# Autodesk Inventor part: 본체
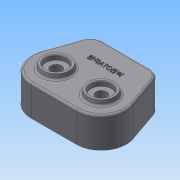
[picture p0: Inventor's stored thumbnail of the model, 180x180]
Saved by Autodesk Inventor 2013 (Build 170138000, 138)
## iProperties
Created: 2014-12
Part Number: 본체
Material: 일반
Document SubType Name: Modeling
Designer: Administrator
Density: 1 g/cm^3
Author: Administrator
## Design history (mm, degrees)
sketch "스케치1"
  geometry: L1 (47, 36)-(-47, 36); L2 (32.527, -68.527)-(-32.527, -68.527); L3 (47, 36)-(66.565, -20.803); L4 (-47, 36)-(-66.565, -20.803); A1 r 36 centre (32.527, -32.527) between (32.527, -68.527) and (66.565, -20.803); A2 r 36 centre (-32.527, -32.527) between (-66.565, -20.803) and (-32.527, -68.527); 3 further points
  constraints: 8 end point, 4 point on circle, 3 tangent, 2 centre point, 2 midpoint, 2 vertical alignment, 1 horizontal, 1 horizontal alignment
  dimensions: "d18" = 94 distance of L1.start L1.end; "d19" = 72 diameter of A1; "d20" = 72 diameter of A2; "d21" = 36 distance from line of point (0, 0) L1; "d22" = 46 distance of A1.centre point (0, 0); "d23" = 90 deg dimension on point (0, 0) A2.centre A1.centre; "d24" = 46 distance of A2.centre point (0, 0)
extrude "돌출1" new body sketch "스케치1" distance "d25" = 44; taper "d26" = 0 deg
sketch "스케치2"
  geometry: L1 (-43.434, 31)-(43.434, 31); L2 (43.434, 31)-(61.837, -22.432); L3 (-43.434, 31)-(-61.837, -22.432); L4 (-66.565, -20.803)-(-47, 36) reference; L5 (47, 36)-(66.565, -20.803) reference; L6 (-32.527, -63.527)-(32.527, -63.527); L7 (-47, 36)-(47, 36) reference; A1 r 36 centre (-32.527, -32.527) between (-66.565, -20.803) and (-32.527, -68.527) reference; A2 r 36 centre (32.527, -32.527) between (32.527, -68.527) and (66.565, -20.803) reference; A3 r 31 centre (-32.527, -32.527) between (-61.837, -22.432) and (-32.527, -63.527); A4 r 31 centre (32.527, -32.527) between (32.527, -63.527) and (61.837, -22.432); 1 further point
  constraints: 8 end point, 4 point on circle, 3 parallel, 3 tangent, 2 centre point, 2 coincident, 1 horizontal
  dimensions: "d29" = 5 distance between parallel lines of L4 L3; "d30" = 5 distance between parallel lines of L7 L1; "d31" = 5 distance between parallel lines of L2 L5
extrude "돌출2" cut sketch "스케치2" distance "d32" = 34; taper "d33" = 0 deg
sketch "스케치3"
  geometry: L1 (47, 36)-(-47, 36) reference; L2 (-47, 36)-(-66.565, -20.803) reference; L3 (-32.527, -68.527)-(32.527, -68.527) reference; L4 (66.565, -20.803)-(47, 36) reference; C1 r 20 at (-32.527, -32.527); C2 r 20 at (32.527, -32.527); A1 r 36 centre (-32.527, -32.527) between (-66.565, -20.803) and (-32.527, -68.527) reference; A2 r 36 centre (32.527, -32.527) between (32.527, -68.527) and (66.565, -20.803) reference; A3 r 36 centre (-32.527, -32.527) between (-66.565, -20.803) and (-32.527, -68.527) reference; A4 r 36 centre (32.527, -32.527) between (32.527, -68.527) and (66.565, -20.803) reference; 1 further point
  constraints: 2 centre point, 2 coincident
  dimensions: "d34" = 40 diameter of C1; "d35" = 40 diameter of C2
extrude "돌출3" join sketch "스케치3" distance "d36" = 7; taper "d37" = -10 deg
sketch "스케치4"
  geometry: A1 r 36 centre (-32.527, -32.527) between (-66.565, -20.803) and (-32.527, -68.527) reference; A2 r 36 centre (32.527, -32.527) between (32.527, -68.527) and (66.565, -20.803) reference; A3 r 24 centre (-32.527, -32.527) between (-21.111, -11.416) and (-11.416, -21.111); A4 r 24 centre (32.527, -32.527) between (11.416, -21.111) and (21.111, -11.416); A5 r 24 centre (0, 0) between (-11.416, -21.111) and (11.416, -21.111); A6 r 24 centre (0, 0) between (21.111, -11.416) and (-21.111, -11.416); 1 further point
  constraints: 8 point on circle, 4 centre point, 3 coincident
  dimensions: "d39" = 48 diameter of A3; "d40" = 48 diameter of A4; "d41" = 24 radius of A6; "d42" = 24 radius of A5
extrude "돌출4" join sketch "스케치4" distance "d43" = 11; taper "d44" = 0 deg
hole "구멍1" diameter "d47" = 20; stored, may be unused: countersink angle "d51" = 90 deg, drill point angle "d53" = 0 deg; dims "d45" = 10, "d46" = 10, "d48" = 6, "d49" = 40, "d50" = 12, "d52" = 15
hole "구멍2" diameter "d56" = 15.5; stored, may be unused: countersink angle "d60" = 90 deg, drill point angle "d62" = 0 deg; dims "d54" = 10, "d55" = 10, "d57" = 6, "d58" = 35, "d59" = 11, "d61" = 21
hole "구멍3" diameter "d65" = 15.5; stored, may be unused: countersink angle "d69" = 90 deg, drill point angle "d71" = 0 deg; dims "d63" = 10, "d64" = 10, "d66" = 6, "d67" = 35, "d68" = 11, "d70" = 21
sketch "스케치5"
  geometry: C1 r 18.766 at (0, 0) reference; C2 r 18.766 at (65.054, 0) reference; C3 r 15 at (0, 0); C4 r 15 at (65.054, 0); 1 further point
  constraints: 2 centre point, 2 coincident
  dimensions: "d72" = 30 diameter of C3; "d73" = 30 diameter of C4
extrude "돌출5" cut sketch "스케치5" distance "d74" = 7; taper "d75" = 0 deg
sketch "스케치6"
  geometry: L1 (-47, 36)-(47, 36) reference; L2 (32.527, -63.527)-(-32.527, -63.527) reference; L3 (-61.837, -22.432)-(-43.434, 31) reference; L4 (43.434, 31)-(61.837, -22.432) reference; A1 r 8 centre (-51.7, 7) between (-54.305, -0.564) and (-49.095, 14.564); A2 r 8 centre (51.7, 7) between (49.095, 14.564) and (54.305, -0.564); A3 r 8 centre (0, -63.527) between (8, -63.527) and (-8, -63.527); 2 further points
  constraints: 8 point on line, 6 point on circle, 3 centre point, 1 coincident, 1 horizontal alignment, 1 midpoint, 1 vertical alignment
  dimensions: "d76" = 16 diameter of A1; "d77" = 16 diameter of A2; "d78" = 29 distance from line of A2.centre L1; "d79" = 16 diameter of A3
extrude "돌출6" join sketch "스케치6" stored distance "d80" = 7; taper "d81" = 0 deg
fillet "모깎기1" dims "d82" = 18, "d83" = 13
sketch "스케치7"
  geometry: A1 r 8 centre (-51.7, 7) between (-54.305, -0.564) and (-49.095, 14.564) reference; A2 r 8 centre (51.7, 7) between (49.095, 14.564) and (54.305, -0.564) reference; A3 r 8 centre (0, -63.527) between (8, -63.527) and (-8, -63.527) reference; 4 further points
  constraints: 3 coincident
hole "구멍4" sketch "스케치7" at (-51.7, 7), (51.7, 7), (0, -63.527) diameter "d84" = 4.134; stored, may be unused: countersink angle "d88" = 90 deg, drill point angle "d90" = 118 deg; dims "d85" = 20, "d86" = 35, "d87" = 11, "d89" = 23
fillet "모깎기2" dims "d91" = 0.3, "d92" = 0.1, "d93" = 3
chamfer "모따기1" distance "d94" = 1; stored, may be unused: second distance "d95" = 2, angle "d96" = 45 deg
sketch "스케치8"
  geometry: L1 (34.162, 36)-(-34.162, 36) reference; 2 further points
  constraints: 1 vertical alignment, 1 other
  dimensions: "d97" = 30 distance from line of point (0, 6) L1
feature "엠보싱1" sketch "스케치8" dims "d98" = 1, "d99" = 0
node "솔리드1"
node "투영된 루프1"
other parameters: "d38" = 48
